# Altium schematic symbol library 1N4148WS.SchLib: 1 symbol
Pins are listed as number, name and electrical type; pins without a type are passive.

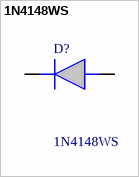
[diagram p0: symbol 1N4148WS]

## 1N4148WS
designator D?
ON Semiconductor Switching Diode, 300mA 75V, 2-Pin SOD-323 1N4148WS; Manufacturer_Name: onsemi; Geometry.Height: 0.9mm
footprint SODFL2512X90N
pins: 1 K, 2 A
